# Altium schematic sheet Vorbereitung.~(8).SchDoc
size A4
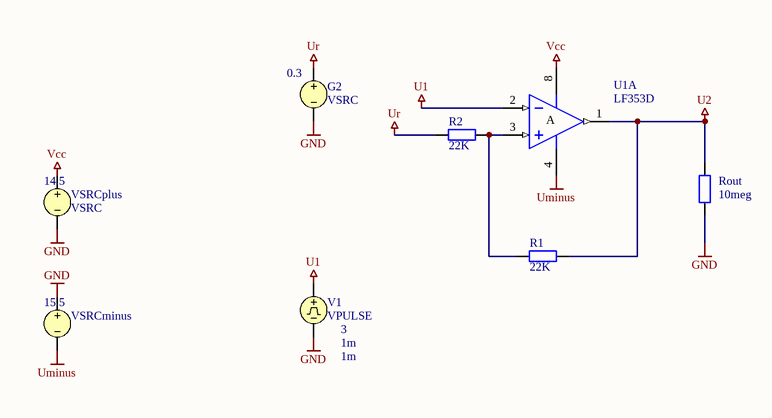
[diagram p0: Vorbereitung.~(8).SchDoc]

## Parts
G2  VSRC  value 0.3
R1  value 22K  [AXIAL-0.4]  (hidden comment: Res2)
R2  value 22K  [AXIAL-0.4]  (hidden comment: Res2)
Rout  value 10meg  [AXIAL-0.4]  (hidden comment: Res2)
U1  LF353D  [D008_L]  (part A of 2)
V1  VPULSE  AC Magnitude: 3  Rise Time: 1m
VSRCminus  value 15.5  (hidden comment: VSRC)
VSRCplus  VSRC  value 14.5

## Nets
GND: G2.2 Rout.1 V1.2 VSRCminus.1 VSRCplus.2
U1: U1.2(IN-) V1.1
U2: R1.1 Rout.2 U1.1(OUT)
Uminus: U1.4(V-) VSRCminus.2
Ur: G2.1 R2.2
Vcc: U1.8(V+) VSRCplus.1
NetR1_2: R1.2 R2.1 U1.3(IN+)

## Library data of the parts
G2 VSRCminus VSRCplus = VSRC: Voltage Source; Note: PCB Footprint - Not required
R1 R2 Rout = Res2: Resistor
U1 = LF353D: Dual Operational Amplifier
V1 = VPULSE: Pulse Voltage Source; Note: PCB Footprint - Not required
